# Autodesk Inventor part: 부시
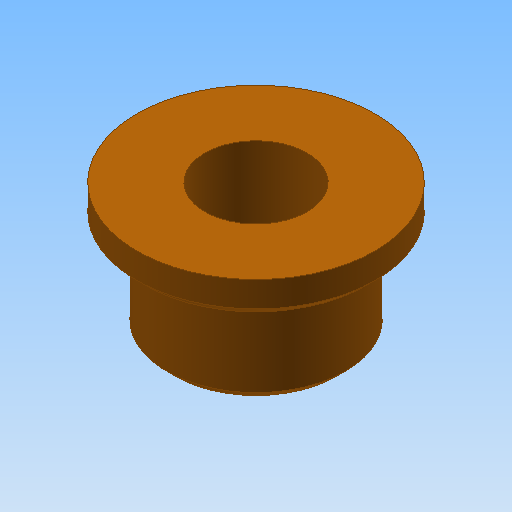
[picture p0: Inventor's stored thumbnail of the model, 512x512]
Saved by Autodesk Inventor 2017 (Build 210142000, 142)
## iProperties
Created: 2016-02
Part Number: 부시
Material: 강철, 연강
Document SubType Name: Modeling
Designer: test
Density: 1 g/cm^3
Appearance: 주황색
Author: test
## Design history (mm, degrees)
sketch "스케치1"
  geometry: C1 r 14 at (0, 0); C2 r 10.5 at (0, 0); 1 further point
  constraints: 2 centre point, 2 coincident
  dimensions: "d0" = 28 diameter of C1; "d1" = 21 diameter of C2
extrude "돌출1" new body sketch "스케치1" distance "d2" = 4; taper "d3" = 0 deg
extrude "돌출2" join sketch "스케치1" distance "d4" = 11; taper "d5" = 0 deg
hole "구멍1" diameter "d8" = 12; stored, may be unused: countersink angle "d12" = 90 deg, drill point angle "d14" = 118 deg; dims "d6" = 10, "d7" = 10, "d9" = 6, "d10" = 4, "d11" = 2, "d13" = 8
chamfer "모따기1" distance "d15" = 1; stored, may be unused: second distance "d16" = 2, angle "d17" = 45 deg
chamfer "모따기2" distance "d18" = 1; stored, may be unused: second distance "d19" = 2, angle "d20" = 45 deg
node "솔리드1"
